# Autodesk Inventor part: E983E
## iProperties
Author: Administrator
Shininess: 47.0
PropertySet Name: _Private Model Information
Created: 2001-03
Part Number: E983E
Document SubType Name: Modeling
Designer: Administrator
Description: Conduit Body, PVC, T, E983E
Material: PVC-Piping
Control State: 0
Master: False
Checked Out: False
PropertySet Name: Design Tracking Control
Density: 1.4000000000000001
Volumn: 935.1293054515494
Area: 3184.64944871468
PropertySet Name: Model Information
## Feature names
1. Body [Extrusion]
2. Base [Extrusion]
3. ThdTabs [Extrusion]
4. LC [Revolution]
5. LCcut [Revolution]
6. LB [Revolution]
7. LBcut [Revolution]
8. End [Revolution]
9. EndCut [Revolution]
10. LL [Extrusion]
11. LLcut [Extrusion]
12. LR [Extrusion]
13. LRcut [Extrusion]
14. Tee [Extrusion]
15. TeeCut [Extrusion]
16. LCclear [Revolution]
17. EndClear [Revolution]
18. Hole1
